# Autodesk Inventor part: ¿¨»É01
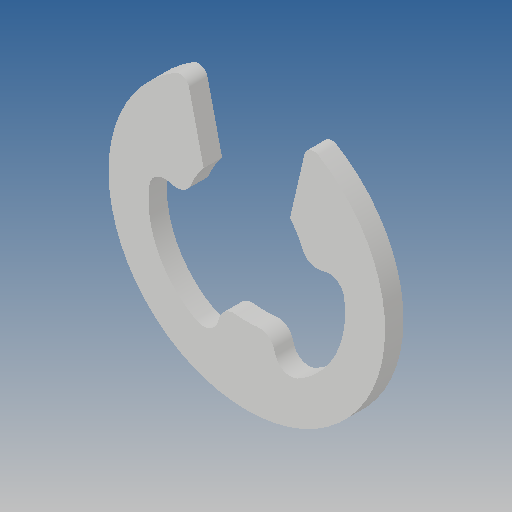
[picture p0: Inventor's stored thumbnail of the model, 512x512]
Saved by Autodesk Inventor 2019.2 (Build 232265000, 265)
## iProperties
Created: 2013-07
Part Number: ¿¨»É01
Material: Ogólny
Document SubType Name: Modeling
Designer: CADENGINEERING4
Density: 1 g/cm^3
Appearance: Domyślna
Author: CADENGINEERING4
Revision Number: ÈÎºÎ
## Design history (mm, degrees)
feature "Í¹Ì¨-À­Éì1"
node "Bryła1"
